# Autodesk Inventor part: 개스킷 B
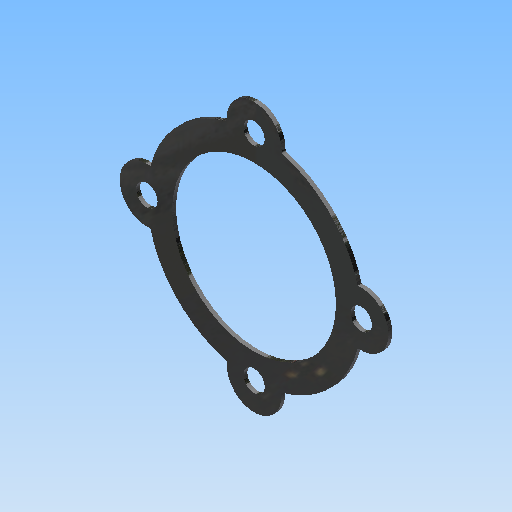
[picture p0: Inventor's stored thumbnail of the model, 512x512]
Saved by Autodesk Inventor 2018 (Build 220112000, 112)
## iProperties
Created: 2020-03
Part Number: 개스킷 B
Material: 고무
Document SubType Name: Modeling
Designer: mduedu
Density: 0.93 g/cm^3
Mass: 1.13966 g
Surface Area: 28.6179 cm^2
Volume: 1.22544 cm^3
Appearance: 고무 - 검은색 - 버전 1.1
Author: mduedu
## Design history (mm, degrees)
sketch "스케치1" dims "d1" = 55
  geometry: C1 r 21 at (0, 0); C2 r 7 at (0, 27.5); C3 r 7 at (-23.816, -13.75); C4 r 7 at (23.816, -13.75); 2 further points
  constraints: 4 centre point, 2 coincident, 2 vertical alignment, 9 other
  dimensions: "d0" = 42 diameter of C1; "d2" = 14 diameter of C2; "d5" = 360 deg dimension on point (0, 0) C2.centre (derived)
extrude "돌출1" new body sketch "스케치1" distance "d7" = 1; taper "d8" = 0 deg
extrude "돌출3" join sketch "스케치1" stored distance "d19" = 10; taper "d20" = 0 deg
fillet "모깎기1" dims "d11" = 1
extrude "돌출2" cut sketch "스케치1" extent not by distance; stored distance "d9" = 1; taper "d10" = 0 deg
sketch "스케치2"
  geometry: C1 r 21 at (0, 0) reference; A1 r 7 centre (0, 27.5) between (6.999, 27.373) and (-6.999, 27.373) reference; A2 r 27.5 centre (0, 0) between (26.609, 6.943) and (7.718, 26.395) reference; A3 r 1 centre (7.999, 27.355) between (6.999, 27.373) and (7.718, 26.395) reference; A4 r 7 centre (0, 27.5) between (6.999, 27.373) and (-6.999, 27.373) reference; A5 r 1 centre (-7.999, 27.355) between (-7.718, 26.395) and (-6.999, 27.373) reference; A6 r 7 centre (0, -27.5) between (-6.943, -26.609) and (6.943, -26.609) reference; A7 r 7 centre (-27.5, 0) between (-26.609, 6.943) and (-26.609, -6.943) reference; A8 r 7 centre (27.5, 0) between (26.609, -6.943) and (26.609, 6.943) reference; A9 r 27.5 centre (0, 0) between (-26.609, -6.943) and (-6.943, -26.609) reference; A10 r 27.5 centre (0, 0) between (6.943, -26.609) and (26.609, -6.943) reference; A11 r 27.5 centre (0, 0) between (-7.718, 26.395) and (-26.609, 6.943) reference; 4 further points
hole "구멍1" sketch "스케치2" diameter "d12" = 5.5; stored, may be unused: countersink angle "d16" = 90 deg, drill point angle "d18" = 118 deg; dims "d13" = 6, "d14" = 4, "d15" = 2, "d17" = 8
node "솔리드1"
pattern_circular "원형 패턴1" dims angle "d22" = 360 deg
node "투영된 루프1"
